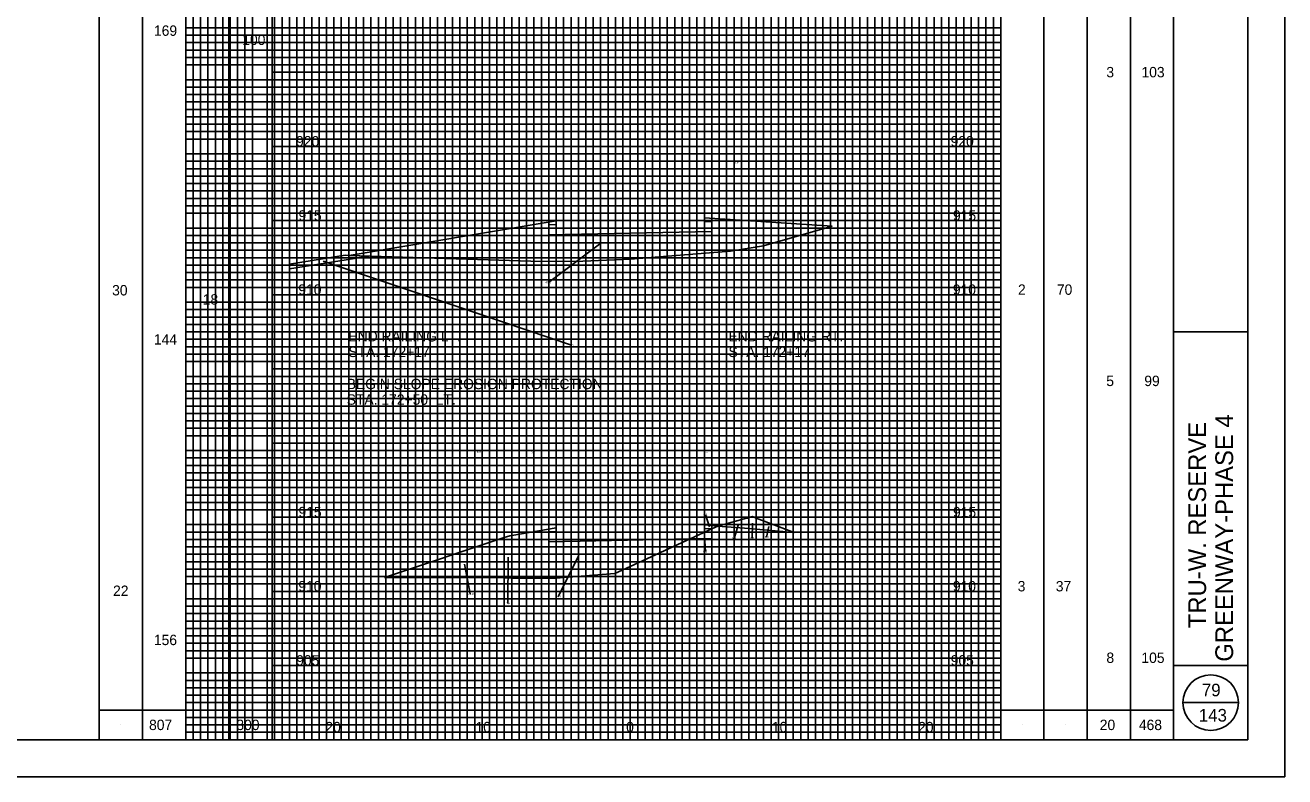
# Model space of a CAD drawing. Extents: x -73 to 160, y -2 to 1877.
# Drawn here: x 75 to 160, y 572.5 to 623.2 of the extents above; entities that cross this region are included whole.
import ezdxf

# ---------------------------------------------------------------- set-up
doc = ezdxf.new("R2010")
doc.units = 0
for name, color, linetype in [('DR_P_Flood_Boundary', 7, 'Continuous'), ('GK_Cells', 7, 'Continuous'), ('RD_X_Fence', 7, 'Continuous'), ('TX_X_5', 7, 'Continuous'), ('UT_P_Water_Cells', 7, 'Continuous'), ('XS_P_Pavt_Layers', 7, 'Continuous'), ('XS_P_Pavt_Surface', 7, 'Continuous'), ('XS_X_Ground_Line', 7, 'Continuous')]:
    doc.layers.add(name, color=color, linetype=linetype)

msp = doc.modelspace()

# ---------------------------------------------------------------- linework, layer by layer
at = {"layer": 'DR_P_Flood_Boundary'}
for p, q in [((95.832, 575), (95.832, 680)), ((100.832, 575), (100.832, 680)), ((105.832, 575), (105.832, 680)), ((110.832, 575), (110.832, 680)), ((115.832, 575), (115.832, 680)), ((120.832, 575), (120.832, 680)), ((125.832, 575), (125.832, 680)), ((130.832, 575), (130.832, 680)), ((135.832, 575), (135.832, 680)), ((91.665, 620), (140.832, 620)), ((91.665, 615), (140.832, 615)), ((91.665, 610), (140.832, 610)), ((91.665, 605), (140.832, 605)), ((91.665, 600), (140.832, 600)), ((91.665, 595), (140.832, 595)), ((91.665, 590), (140.832, 590)), ((91.665, 585), (140.832, 585)), ((91.665, 580), (140.832, 580))]:
    msp.add_line(p, q, dxfattribs=at)
at = {"layer": 'GK_Cells'}
for p, q in [((152.5, 575), (152.5, 680)), ((152.5, 602.5), (157.5, 602.5)), ((152.5, 580), (157.5, 580))]:
    msp.add_line(p, q, dxfattribs=at)
msp.add_lwpolyline([(0, 680), (157.5, 680), (157.5, 575), (0, 575)], close=True, dxfattribs=at)
at = {"layer": 'RD_X_Fence'}
for p, q in [((110.832, 609.98), (96.872, 607.653)), ((110.332, 609.72), (110.832, 609.73)), ((110.332, 609.053), (110.332, 609.72)), ((129.459, 609.619), (120.832, 610.18)), ((120.832, 609.93), (121.332, 609.94)), ((121.332, 609.94), (121.332, 609.273)), ((121.332, 609.273), (110.332, 609.053)), ((113.838, 608.477), (110.308, 605.831)), ((92.833, 606.742), (98.207, 607.61)), ((92.833, 607.072), (92.833, 606.742)), ((95.118, 607.262), (111.87, 601.607)), ((98.207, 607.61), (96.872, 607.653)), ((121.186, 589.349), (120.917, 590.163)), ((123.832, 589.932), (123.677, 589.932)), ((123.832, 589.231), (123.832, 589.932)), ((124.332, 589.19), (124.332, 589.943)), ((126.902, 588.977), (124.332, 589.943)), ((124.332, 589.943), (124.332, 589.19)), ((110.832, 589.28), (107.832, 588.78)), ((121.332, 589.217), (119.871, 588.544)), ((121.74, 589.405), (120.832, 589.48)), ((120.832, 589.23), (121.332, 589.24)), ((121.332, 588.573), (121.332, 589.217)), ((121.341, 589.221), (121.74, 589.405)), ((121.74, 589.405), (123.832, 589.231)), ((123.132, 589.535), (122.841, 588.557)), ((123.832, 589.231), (124.332, 589.19)), ((124.083, 589.605), (124.06, 588.588)), ((124.332, 589.19), (126.902, 588.977)), ((125.189, 589.37), (125.02, 588.664)), ((107.332, 588.636), (99.245, 585.94)), ((107.698, 588.758), (107.332, 588.636)), ((107.332, 585.906), (107.332, 588.636)), ((107.332, 588.636), (107.332, 585.906)), ((107.832, 588.78), (107.698, 588.758)), ((107.832, 585.903), (107.832, 588.78)), ((107.832, 588.78), (107.832, 585.903)), ((110.332, 589.02), (110.832, 589.03)), ((110.332, 588.353), (110.332, 589.02)), ((119.871, 588.544), (110.332, 588.353)), ((119.871, 588.544), (121.332, 588.573)), ((120.845, 588.778), (120.907, 587.688)), ((112.355, 587.418), (110.957, 584.666)), ((104.637, 586.827), (105.028, 584.833)), ((107.585, 587.311), (107.576, 584.19)), ((99.245, 585.94), (107.332, 585.906)), ((107.332, 585.906), (107.832, 585.903))]:
    msp.add_line(p, q, dxfattribs=at)
for points in [[(96.872, 607.653), (109.849, 607.234), (112.619, 607.269), (115.832, 607.407), (122.585, 607.934), (124.822, 608.311), (129.459, 609.619)], [(110.832, 609.73), (110.832, 609.876), (110.832, 609.98)], [(120.832, 610.18), (120.832, 610.076), (120.832, 609.93)], [(96.872, 607.653), (96.584, 607.663), (92.833, 607.072)], [(123.677, 589.932), (123.667, 589.929), (121.74, 589.405)], [(124.332, 589.943), (124.074, 590.04), (123.832, 589.975)], [(123.832, 589.975), (123.832, 589.932), (123.832, 589.231)], [(110.832, 589.03), (110.832, 589.176), (110.832, 589.28)], [(120.832, 589.48), (120.832, 589.376), (120.832, 589.23)], [(121.332, 589.24), (121.341, 589.221)], [(107.832, 585.903), (110.818, 585.891), (114.788, 586.203), (115.833, 586.684), (119.871, 588.544)]]:
    msp.add_lwpolyline(points, dxfattribs=at)
at = {"layer": 'TX_X_5'}
msp.add_lwpolyline([(-10, 572.5), (160, 572.5), (160, 682.5), (-10, 682.5)], close=True, dxfattribs=at)
at = {"layer": 'UT_P_Water_Cells'}
for p, q in [((86.332, 575), (86.332, 680)), ((86.832, 575), (86.832, 680)), ((87.332, 575), (87.332, 680)), ((87.832, 575), (87.832, 680)), ((88.332, 575), (88.332, 680)), ((88.832, 575), (88.832, 680)), ((89.332, 575), (89.332, 680)), ((89.832, 575), (89.832, 680)), ((90.332, 575), (90.332, 680)), ((91.332, 575), (91.332, 680)), ((91.832, 575), (91.832, 680)), ((92.332, 575), (92.332, 680)), ((92.832, 575), (92.832, 680)), ((93.332, 575), (93.332, 680)), ((93.832, 575), (93.832, 680)), ((94.332, 575), (94.332, 680)), ((94.832, 575), (94.832, 680)), ((95.332, 575), (95.332, 680)), ((96.332, 575), (96.332, 680)), ((96.832, 575), (96.832, 680)), ((97.332, 575), (97.332, 680)), ((97.832, 575), (97.832, 680)), ((98.332, 575), (98.332, 680)), ((98.832, 575), (98.832, 680)), ((99.332, 575), (99.332, 680)), ((99.832, 575), (99.832, 680)), ((100.332, 575), (100.332, 680)), ((101.332, 575), (101.332, 680)), ((101.832, 575), (101.832, 680)), ((102.332, 575), (102.332, 680)), ((102.832, 575), (102.832, 680)), ((103.332, 575), (103.332, 680)), ((103.832, 575), (103.832, 680)), ((104.332, 575), (104.332, 680)), ((104.832, 575), (104.832, 680)), ((105.332, 575), (105.332, 680)), ((106.332, 575), (106.332, 680)), ((106.832, 575), (106.832, 680)), ((107.332, 575), (107.332, 680)), ((107.832, 575), (107.832, 680)), ((108.332, 575), (108.332, 680)), ((108.832, 575), (108.832, 680)), ((109.332, 575), (109.332, 680)), ((109.832, 575), (109.832, 680)), ((110.332, 575), (110.332, 680)), ((111.332, 575), (111.332, 680)), ((111.832, 575), (111.832, 680)), ((112.332, 575), (112.332, 680)), ((112.832, 575), (112.832, 680)), ((113.332, 575), (113.332, 680)), ((113.832, 575), (113.832, 680)), ((114.332, 575), (114.332, 680)), ((114.832, 575), (114.832, 680)), ((115.332, 575), (115.332, 680)), ((116.332, 575), (116.332, 680)), ((116.832, 575), (116.832, 680)), ((117.332, 575), (117.332, 680)), ((117.832, 575), (117.832, 680)), ((118.332, 575), (118.332, 680)), ((118.832, 575), (118.832, 680)), ((119.332, 575), (119.332, 680)), ((119.832, 575), (119.832, 680)), ((120.332, 575), (120.332, 680)), ((121.332, 575), (121.332, 680)), ((121.832, 575), (121.832, 680)), ((122.332, 575), (122.332, 680)), ((122.832, 575), (122.832, 680)), ((123.332, 575), (123.332, 680)), ((123.832, 575), (123.832, 680)), ((124.332, 575), (124.332, 680)), ((124.832, 575), (124.832, 680)), ((125.332, 575), (125.332, 680)), ((126.332, 575), (126.332, 680)), ((126.832, 575), (126.832, 680)), ((127.332, 575), (127.332, 680)), ((127.832, 575), (127.832, 680)), ((128.332, 575), (128.332, 680)), ((128.832, 575), (128.832, 680)), ((129.332, 575), (129.332, 680)), ((129.832, 575), (129.832, 680)), ((130.332, 575), (130.332, 680)), ((131.332, 575), (131.332, 680)), ((131.832, 575), (131.832, 680)), ((132.332, 575), (132.332, 680)), ((132.832, 575), (132.832, 680)), ((133.332, 575), (133.332, 680)), ((133.832, 575), (133.832, 680)), ((134.332, 575), (134.332, 680)), ((134.832, 575), (134.832, 680)), ((135.332, 575), (135.332, 680)), ((136.332, 575), (136.332, 680)), ((136.832, 575), (136.832, 680)), ((137.332, 575), (137.332, 680)), ((137.832, 575), (137.832, 680)), ((138.332, 575), (138.332, 680)), ((138.832, 575), (138.832, 680)), ((139.332, 575), (139.332, 680)), ((139.832, 575), (139.832, 680)), ((140.332, 575), (140.332, 680)), ((85.832, 623), (140.832, 623)), ((85.832, 622.5), (140.832, 622.5)), ((85.832, 622), (140.832, 622)), ((85.832, 621.5), (140.832, 621.5)), ((85.832, 621), (140.832, 621)), ((85.832, 620.5), (140.832, 620.5)), ((85.832, 619.5), (140.832, 619.5)), ((85.832, 619), (140.832, 619)), ((85.832, 618.5), (140.832, 618.5)), ((85.832, 618), (140.832, 618)), ((85.832, 617.5), (140.832, 617.5)), ((85.832, 617), (140.832, 617)), ((85.832, 616.5), (140.832, 616.5)), ((85.832, 616), (140.832, 616)), ((85.832, 615.5), (140.832, 615.5)), ((85.832, 614.5), (140.832, 614.5)), ((85.832, 614), (140.832, 614)), ((85.832, 613.5), (140.832, 613.5)), ((85.832, 613), (140.832, 613)), ((85.832, 612.5), (140.832, 612.5)), ((85.832, 612), (140.832, 612)), ((85.832, 611.5), (140.832, 611.5)), ((85.832, 611), (140.832, 611)), ((85.832, 610.5), (140.832, 610.5)), ((85.832, 609.5), (140.832, 609.5)), ((85.832, 609), (140.832, 609)), ((85.832, 608.5), (140.832, 608.5)), ((85.832, 608), (140.832, 608)), ((85.832, 607.5), (140.832, 607.5)), ((85.832, 607), (140.832, 607)), ((85.832, 606.5), (140.832, 606.5)), ((85.832, 606), (140.832, 606)), ((85.832, 605.5), (140.832, 605.5)), ((85.832, 604.5), (140.832, 604.5)), ((85.832, 604), (140.832, 604)), ((85.832, 603.5), (140.832, 603.5)), ((85.832, 603), (140.832, 603)), ((85.832, 602.5), (140.832, 602.5)), ((85.832, 602), (140.832, 602)), ((85.832, 601.5), (140.832, 601.5)), ((85.832, 601), (140.832, 601)), ((85.832, 600.5), (140.832, 600.5)), ((85.832, 599.5), (140.832, 599.5)), ((85.832, 599), (140.832, 599)), ((85.832, 598.5), (140.832, 598.5)), ((85.832, 598), (140.832, 598)), ((85.832, 597.5), (140.832, 597.5)), ((85.832, 597), (140.832, 597)), ((85.832, 596.5), (140.832, 596.5)), ((85.832, 596), (140.832, 596)), ((85.832, 595.5), (140.832, 595.5)), ((85.832, 594.5), (140.832, 594.5)), ((85.832, 594), (140.832, 594)), ((85.832, 593.5), (140.832, 593.5)), ((85.832, 593), (140.832, 593)), ((85.832, 592.5), (140.832, 592.5)), ((85.832, 592), (140.832, 592)), ((85.832, 591.5), (140.832, 591.5)), ((85.832, 591), (140.832, 591)), ((85.832, 590.5), (140.832, 590.5)), ((85.832, 589.5), (140.832, 589.5)), ((85.832, 589), (140.832, 589)), ((85.832, 588.5), (140.832, 588.5)), ((85.832, 588), (140.832, 588)), ((85.832, 587.5), (140.832, 587.5)), ((85.832, 587), (140.832, 587)), ((85.832, 586.5), (140.832, 586.5)), ((85.832, 586), (140.832, 586)), ((85.832, 585.5), (140.832, 585.5)), ((85.832, 584.5), (140.832, 584.5)), ((85.832, 584), (140.832, 584)), ((85.832, 583.5), (140.832, 583.5)), ((85.832, 583), (140.832, 583)), ((85.832, 582.5), (140.832, 582.5)), ((85.832, 582), (140.832, 582)), ((85.832, 581.5), (140.832, 581.5)), ((85.832, 581), (140.832, 581)), ((85.832, 580.5), (140.832, 580.5)), ((85.832, 579.5), (140.832, 579.5)), ((85.832, 579), (140.832, 579)), ((85.832, 578.5), (140.832, 578.5)), ((85.832, 578), (140.832, 578)), ((85.832, 577.5), (140.832, 577.5)), ((85.832, 577), (140.832, 577)), ((85.832, 576.5), (140.832, 576.5)), ((85.832, 576), (140.832, 576)), ((85.832, 575.5), (140.832, 575.5))]:
    msp.add_line(p, q, dxfattribs=at)
at = {"layer": 'XS_X_Ground_Line'}
for p, q in [((80, 575), (80, 680)), ((85.832, 575), (85.832, 680)), ((85.832, 575), (85.832, 680)), ((91.665, 575), (91.665, 680)), ((140.832, 575), (140.832, 680)), ((146.667, 575), (146.667, 680)), ((82.916, 575), (82.916, 678.75)), ((143.75, 575), (143.75, 678.75)), ((149.583, 575), (149.583, 678.75)), ((88.749, 575), (88.749, 676.667)), ((155, 591.458), (155, 591.458)), ((153.125, 577.5), (156.875, 577.5)), ((155, 577.925), (155, 577.925)), ((80, 577), (91.665, 577)), ((140.832, 577), (152.5, 577)), ((81.458, 576.03), (81.458, 576.03)), ((84.374, 576.03), (84.374, 576.03)), ((142.291, 576), (142.291, 576)), ((145.209, 576), (145.209, 576)), ((148.125, 576), (148.125, 576)), ((151.042, 576), (151.042, 576)), ((155, 576.225), (155, 576.225))]:
    msp.add_line(p, q, dxfattribs=at)
msp.add_circle((155, 577.5), 1.875, dxfattribs=at)

# ---------------------------------------------------------------- texts
at = {"layer": 'RD_X_Fence'}
for s, p in [('14.2', (104.925, 614.458)), ('8.6', (122.857, 613.865)), ('47.6', (110.097, 605.761)), ('1.5', (111.738, 601.537)), ('8.9', (105.472, 594.356)), ('3.2', (109.136, 594.305)), ('6.1', (120.79, 594.331)), ('0.2', (120.765, 590.093)), ('0.8', (122.687, 588.487)), ('0.4', (123.908, 588.518)), ('1.0', (124.895, 588.594)), ('0.5', (120.755, 587.618)), ('11.0', (104.871, 584.763)), ('1.4', (107.458, 584.12)), ('24.1', (110.778, 584.596))]:
    msp.add_text(s, height=0.14, dxfattribs=at).set_placement(p)
at = {"layer": 'XS_P_Pavt_Layers'}
for s, p in [('79', (154.404, 577.925)), ('143', (154.197, 576.225))]:
    msp.add_text(s, height=0.85, dxfattribs=at).set_placement(p)
at = {"layer": 'XS_P_Pavt_Surface'}
for s, p in [('169', (83.691, 622.461)), ('100', (89.647, 621.842)), ('3', (147.958, 619.662)), ('103', (150.328, 619.662)), ('920', (93.281, 615)), ('920', (137.449, 615)), ('915', (93.441, 610)), ('915', (137.609, 610)), ('30', (80.866, 604.957)), ('910', (93.43, 605)), ('910', (137.598, 605)), ('2', (141.994, 605)), ('70', (144.62, 605)), ('18', (86.98, 604.338)), ('144', (83.685, 601.641)), ('END RAILING LT.', (96.808, 601.851)), ('END RAILING RT.', (122.456, 601.851)), ('STA. 172+17', (96.808, 600.801)), ('STA. 172+17', (122.456, 600.801)), ('BEGIN SLOPE EROSION PROTECTION', (96.696, 598.637)), ('5', (147.952, 598.844)), ('99', (150.518, 598.844)), ('STA. 172+50, LT.', (96.696, 597.587)), ('915', (93.441, 590)), ('915', (137.609, 590)), ('910', (93.43, 585)), ('910', (137.598, 585)), ('3', (141.974, 585)), ('37', (144.546, 585)), ('22', (80.929, 584.695)), ('156', (83.685, 581.378)), ('905', (93.287, 580)), ('905', (137.454, 580)), ('8', (147.963, 580.176)), ('105', (150.323, 580.176)), ('807', (83.358, 575.65)), ('300', (89.249, 575.65)), ('20', (147.513, 575.65)), ('468', (150.152, 575.65)), ('20', (95.257, 575.5)), ('10', (105.389, 575.5)), ('0', (115.554, 575.5)), ('0', (115.554, 575.5)), ('10', (125.389, 575.5)), ('20', (135.257, 575.5))]:
    msp.add_text(s, height=0.7, dxfattribs=at).set_placement(p)
for s, p in [('GREENWAY-PHASE 4', (156.512, 580.261)), ('TRU-W. RESERVE', (154.688, 582.519))]:
    msp.add_text(s, height=1.2, rotation=90, dxfattribs=at).set_placement(p)
at = {"layer": 'XS_X_Ground_Line'}
msp.add_text('143', height=0.85, dxfattribs=at).set_placement((154.197, 576.225))

doc.saveas('drawing.dxf')
